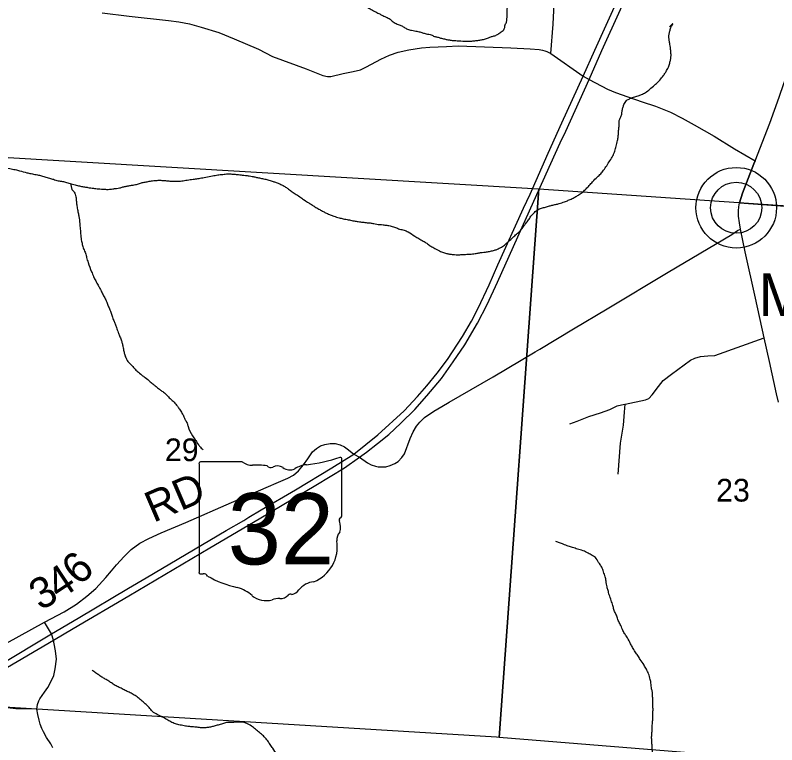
# Model space of a CAD drawing. Extents: x -13.7 to 34, y 0 to 32.3.
# Drawn here: x 27.041 to 28.447, y 18.977 to 20.324 of the extents above; entities that cross this region are included whole.
import ezdxf

# ---------------------------------------------------------------- set-up
doc = ezdxf.new("R2010")
doc.units = 0
for name, color, linetype in [('GM_X_Corporation', 7, 'Continuous'), ('GM_X_County_Road', 7, 'Continuous'), ('GM_X_County_Road_Text', 7, 'Continuous'), ('GM_X_Minor_River', 7, 'Continuous'), ('GM_X_Section_Text', 7, 'Continuous'), ('GM_X_State_Location', 7, 'Continuous'), ('GM_X_State_Route', 7, 'Continuous'), ('GM_X_State_Shield', 7, 'Continuous'), ('GM_X_Township_Road', 7, 'Continuous'), ('GM_X_Unincorporated', 7, 'Continuous'), ('GM_X_Unincorporated_Location', 7, 'Continuous'), ('GM_X_Unincorporated_Text', 7, 'Continuous')]:
    doc.layers.add(name, color=color, linetype=linetype)

msp = doc.modelspace()

# ---------------------------------------------------------------- linework, layer by layer
at = {"layer": 'GM_X_Corporation'}
for points in [[(28.0076, 20.0028), (27.9343, 18.9903), (27.9295, 18.9907), (26.9188, 19.0522), (26.9853, 20.0635)], [(28.0076, 20.0028), (29.0337, 19.933), (28.9612, 18.9069), (27.9343, 18.9903)]]:
    msp.add_lwpolyline(points, close=True, dxfattribs=at)
at = {"layer": 'GM_X_County_Road'}
msp.add_line((27.1077, 19.1812), (27.0948, 19.2028), dxfattribs=at)
for points in [[(27.842, 19.6094), (27.9232, 19.6562), (28.0009, 19.7023), (28.0095, 19.7069), (28.0717, 19.7447), (28.1337, 19.7814), (28.2465, 19.8492), (28.3635, 19.9188), (28.3743, 19.9264), (28.3795, 19.9283)], [(27.5185, 19.4575), (27.5443, 19.4687), (27.5547, 19.4747), (27.5636, 19.4823), (27.5731, 19.4937), (27.5811, 19.5048), (27.5896, 19.5174), (27.5968, 19.5238), (27.6045, 19.5284), (27.6127, 19.5313), (27.622, 19.5329), (27.6315, 19.5327), (27.641, 19.5302), (27.6489, 19.5267), (27.6562, 19.5214), (27.6657, 19.5134), (27.6766, 19.5079), (27.6914, 19.4974), (27.6982, 19.4935), (27.7061, 19.491), (27.7108, 19.49), (27.7177, 19.4898), (27.7251, 19.49), (27.7331, 19.4924), (27.7414, 19.4958), (27.7478, 19.4997), (27.7544, 19.5069), (27.7594, 19.5139), (27.7697, 19.5422), (27.7755, 19.5544), (27.7814, 19.5647), (27.7877, 19.5724), (27.7964, 19.5808), (27.8135, 19.5928), (27.8282, 19.6015), (27.842, 19.6094)], [(27.2189, 19.2978), (27.2281, 19.3088), (27.242, 19.3245), (27.2552, 19.3373), (27.2711, 19.3487), (27.2876, 19.3574), (27.3101, 19.3677), (27.3556, 19.3871), (27.4404, 19.4241), (27.513, 19.4551), (27.5185, 19.4575)], [(26.7689, 19.0326), (26.8253, 19.0552), (26.8652, 19.0766), (26.8873, 19.0892), (26.9488, 19.1225), (27.0948, 19.2028), (27.131, 19.2223), (27.154, 19.2361), (27.1734, 19.251), (27.1897, 19.2652), (27.2083, 19.2853), (27.2189, 19.2978)]]:
    msp.add_lwpolyline(points, dxfattribs=at)
at = {"layer": 'GM_X_Minor_River'}
msp.add_lwpolyline([(27.1427, 20.0128), (27.1457, 20.002)], dxfattribs=at)
for points in [[(27.6709, 20.3481), (27.678, 20.3445), (27.6877, 20.3396), (27.6959, 20.3355), (27.7045, 20.3307), (27.7123, 20.3266), (27.7179, 20.3238), (27.7254, 20.3201), (27.7329, 20.3161), (27.7384, 20.3113), (27.7462, 20.3073), (27.753, 20.3048), (27.7586, 20.3015), (27.7649, 20.2979), (27.7724, 20.2958), (27.7781, 20.2948), (27.7864, 20.293), (27.7928, 20.2913), (27.7992, 20.2892), (27.809, 20.2873), (27.8146, 20.2845), (27.8202, 20.2832), (27.8262, 20.2815), (27.8334, 20.2797), (27.8394, 20.2784), (27.8455, 20.2774), (27.8545, 20.2767), (27.8633, 20.276), (27.8788, 20.2755), (27.8857, 20.2761), (27.8933, 20.2769), (27.9001, 20.2779), (27.9074, 20.2795), (27.9143, 20.2816), (27.9201, 20.284), (27.9262, 20.2857), (27.9324, 20.2889), (27.9382, 20.2929), (27.9437, 20.2984), (27.945, 20.3041), (27.9475, 20.3109), (27.9485, 20.3165), (27.949, 20.3321), (27.9496, 20.3378), (27.9505, 20.3438), (27.9515, 20.3495), (27.9524, 20.3555), (27.9465, 20.3588)], [(28.2495, 20.2697), (28.2482, 20.2766), (28.2476, 20.2827), (28.2478, 20.2884), (28.2492, 20.294), (28.2513, 20.3012), (28.2549, 20.3079), (28.2487, 20.3024)], [(27.6961, 19.9401), (27.7029, 19.9388), (27.7138, 19.9372), (27.7199, 19.9367), (27.7267, 19.9357), (27.735, 19.9343), (27.7429, 19.9317), (27.7504, 19.9288), (27.7586, 19.9266), (27.7661, 19.9237), (27.7788, 19.9157), (27.7859, 19.9113), (27.794, 19.9065), (27.8007, 19.9025), (27.8067, 19.8981), (27.8134, 19.8944), (27.8227, 19.8892), (27.8294, 19.8863), (27.8369, 19.8838), (27.8426, 19.8825), (27.849, 19.8819), (27.8551, 19.8813), (27.8615, 19.8815), (27.8691, 19.882), (27.8802, 19.8824), (27.8897, 19.8836), (27.897, 19.8848), (27.9031, 19.8858), (27.9088, 19.8864), (27.9164, 19.8876), (27.9237, 19.8893), (27.9302, 19.8913), (27.9383, 19.8956), (27.9457, 19.9007), (27.9516, 19.9058), (27.9594, 19.9132), (27.9664, 19.9194), (27.9735, 19.926), (27.9794, 19.9338), (27.9834, 19.9393), (27.9882, 19.9456), (27.993, 19.9523), (27.9977, 19.9578), (28.0043, 19.9637), (28.0105, 19.9665), (28.0182, 19.9689), (28.0255, 19.971), (28.0316, 19.9727), (28.0385, 19.9743), (28.045, 19.9757), (28.055, 19.9791), (28.0619, 19.9819), (28.0692, 19.9851), (28.0758, 19.9887), (28.082, 19.9923), (28.089, 19.9977), (28.0949, 20.0032), (28.1004, 20.0091), (28.1067, 20.0161), (28.1157, 20.025), (28.1216, 20.0308), (28.1271, 20.0375), (28.1327, 20.0457), (28.1387, 20.055), (28.144, 20.0639), (28.1477, 20.0729), (28.1502, 20.0816), (28.1529, 20.0925), (28.1539, 20.0997), (28.1545, 20.1072), (28.1551, 20.1144), (28.1557, 20.1213), (28.1556, 20.1277), (28.1576, 20.1333), (28.1601, 20.1393), (28.1611, 20.1461), (28.1625, 20.1529), (28.1646, 20.1586), (28.1694, 20.166), (28.1756, 20.1696), (28.1848, 20.1731), (28.1925, 20.1755), (28.1986, 20.1779), (28.2063, 20.1822), (28.2145, 20.1888), (28.2231, 20.1961), (28.229, 20.202), (28.2357, 20.2101), (28.2401, 20.2157), (28.2433, 20.2213), (28.2474, 20.2295), (28.2495, 20.237), (28.2509, 20.2431), (28.2515, 20.2491), (28.251, 20.2567), (28.2504, 20.264), (28.2495, 20.2697)], [(26.9187, 20.0593), (26.933, 20.0642), (26.9433, 20.0646), (26.9528, 20.065), (26.9592, 20.0656), (26.9664, 20.065), (26.9736, 20.0628), (26.9803, 20.0603), (26.9904, 20.055), (26.9997, 20.0498), (27.0102, 20.0456), (27.0313, 20.0404), (27.0411, 20.0385), (27.049, 20.0364), (27.0626, 20.0329), (27.0701, 20.0311), (27.0799, 20.0293), (27.0874, 20.0275), (27.0957, 20.025), (27.104, 20.0228), (27.1115, 20.0206), (27.1201, 20.0181), (27.1281, 20.0167), (27.1356, 20.0149), (27.1443, 20.0123), (27.1537, 20.0097), (27.1616, 20.008), (27.1691, 20.0066), (27.1752, 20.0056), (27.1854, 20.0041), (27.1941, 20.0031), (27.2058, 20.0023), (27.2126, 20.0021), (27.221, 20.003), (27.2279, 20.0039), (27.2336, 20.0048), (27.2397, 20.0065), (27.2458, 20.0078), (27.2523, 20.0091), (27.2588, 20.0101), (27.2665, 20.0117), (27.2738, 20.0141), (27.281, 20.0154), (27.2883, 20.0171), (27.2967, 20.0183), (27.305, 20.0188), (27.3141, 20.0185), (27.3221, 20.0178), (27.3308, 20.0172), (27.3411, 20.0172), (27.3509, 20.018), (27.3612, 20.0196), (27.3719, 20.0211), (27.3803, 20.0224), (27.3895, 20.024), (27.4021, 20.0266), (27.4078, 20.0275), (27.417, 20.0291), (27.4265, 20.03), (27.4349, 20.0308), (27.4425, 20.0302), (27.4512, 20.0295), (27.4599, 20.0285), (27.4659, 20.0279), (27.4727, 20.0269), (27.4784, 20.026), (27.4848, 20.0246), (27.492, 20.0232), (27.4995, 20.0215), (27.5074, 20.0197), (27.5153, 20.0171), (27.5213, 20.0154), (27.5277, 20.0129), (27.5344, 20.0097), (27.54, 20.0064), (27.5455, 20.0025), (27.5522, 19.9973), (27.5597, 19.9929), (27.5682, 19.9869), (27.5745, 19.9825), (27.5827, 19.9773), (27.5894, 19.9729), (27.5957, 19.9689), (27.6031, 19.9648), (27.6095, 19.9612), (27.6154, 19.958), (27.6226, 19.9551), (27.6289, 19.9526), (27.6387, 19.9496), (27.6466, 19.9478), (27.6557, 19.946), (27.6643, 19.9442), (27.6723, 19.9428), (27.6802, 19.9418), (27.6885, 19.9407), (27.6961, 19.9401)], [(27.1457, 20.002), (27.1498, 19.997), (27.153, 19.9885), (27.1538, 19.9794), (27.1547, 19.9714), (27.1563, 19.9629), (27.1579, 19.9549), (27.1592, 19.9484), (27.1598, 19.9419), (27.1606, 19.9317), (27.1617, 19.9202), (27.1628, 19.9088), (27.1648, 19.9004), (27.1672, 19.8923), (27.1707, 19.8842), (27.1728, 19.8762), (27.1755, 19.867), (27.1818, 19.85), (27.1856, 19.8408), (27.1895, 19.8331), (27.1938, 19.825), (27.1974, 19.8188), (27.2003, 19.813), (27.2042, 19.8056), (27.2081, 19.7979), (27.2113, 19.7902), (27.2141, 19.7833), (27.2176, 19.7755), (27.22, 19.7679), (27.2228, 19.7598), (27.2256, 19.7536), (27.2277, 19.7471), (27.2312, 19.7379), (27.2336, 19.7317), (27.2364, 19.724), (27.2385, 19.7179), (27.2398, 19.7118), (27.2414, 19.7033), (27.2431, 19.6965), (27.2455, 19.6903), (27.2488, 19.6845), (27.2546, 19.6786), (27.2609, 19.6712), (27.2668, 19.666), (27.2745, 19.6593), (27.2808, 19.6546), (27.29, 19.647), (27.2967, 19.6415), (27.3022, 19.6371), (27.3089, 19.6316), (27.3148, 19.6276), (27.3204, 19.6225), (27.327, 19.6158), (27.3343, 19.6091), (27.3402, 19.6021), (27.3442, 19.5962), (27.3488, 19.5889), (27.3524, 19.5823), (27.3549, 19.5765), (27.3581, 19.5707), (27.3602, 19.5642), (27.368, 19.5472), (27.3734, 19.5398), (27.377, 19.5336)], [(27.377, 19.5336), (27.3814, 19.5278), (27.3876, 19.5211)], [(28.2164, 18.9767), (28.2159, 18.9847), (28.2158, 18.9934), (28.2165, 19.0014), (28.217, 19.0162), (28.218, 19.0241), (28.2179, 19.0325), (28.2182, 19.0408), (28.2181, 19.0492), (28.218, 19.0572), (28.2175, 19.0651), (28.217, 19.0735), (28.2157, 19.08), (28.2145, 19.0903), (28.2132, 19.0972), (28.2102, 19.1079), (28.2059, 19.1164), (28.2016, 19.1238), (28.1947, 19.1343), (28.19, 19.1413), (28.1853, 19.1483), (28.1806, 19.1564), (28.1767, 19.163), (28.171, 19.1742), (28.1666, 19.1808), (28.1627, 19.1874), (28.1588, 19.1966), (28.1549, 19.2044), (28.1521, 19.2121), (28.1489, 19.2194), (28.1461, 19.2263), (28.1441, 19.2336), (28.141, 19.2432), (28.1375, 19.2536), (28.1352, 19.2616), (28.1335, 19.2681), (28.1316, 19.2788), (28.1299, 19.2869), (28.1268, 19.2961), (28.1237, 19.3045), (28.1193, 19.3111), (28.1136, 19.3204), (28.1062, 19.3264), (28.0987, 19.3304), (28.089, 19.3349), (28.0788, 19.3379), (28.0698, 19.3409), (28.0619, 19.3434), (28.0526, 19.3468), (28.0458, 19.3493), (28.0387, 19.3522)], [(27.4309, 19.0175), (27.4236, 19.0155), (27.4155, 19.0131), (27.4083, 19.011), (27.4014, 19.0094), (27.3945, 19.0084), (27.3876, 19.0079), (27.3786, 19.0086), (27.3702, 19.0096), (27.3631, 19.0102), (27.3555, 19.0113), (27.3453, 19.0131), (27.3366, 19.0153), (27.328, 19.019), (27.3206, 19.0234), (27.3124, 19.0279), (27.3031, 19.0327), (27.2945, 19.038), (27.2879, 19.0454), (27.2809, 19.0525), (27.2736, 19.0588), (27.2658, 19.0651), (27.2584, 19.0696), (27.2513, 19.0736), (27.2438, 19.0769), (27.2367, 19.0809), (27.2292, 19.0842), (27.2218, 19.0886), (27.2155, 19.093), (27.2088, 19.097), (27.2024, 19.1007), (27.1958, 19.1051), (27.1894, 19.1094), (27.1828, 19.1142)], [(28.0645, 18.3997), (28.0617, 18.407), (28.0555, 18.4167), (28.0485, 18.4234), (28.0422, 18.4281), (28.0359, 18.431), (28.0288, 18.4343), (28.0224, 18.436), (28.0156, 18.4377), (28.0088, 18.4399), (28.0007, 18.4455), (27.9936, 18.451), (27.9867, 18.4588), (27.979, 18.4659), (27.9726, 18.4699), (27.9676, 18.4792), (27.9638, 18.4885), (27.9606, 18.495), (27.9582, 18.5031), (27.9529, 18.5151), (27.9463, 18.5236), (27.9413, 18.5322), (27.9381, 18.5391), (27.933, 18.5469), (27.9268, 18.5543), (27.9206, 18.5606), (27.9111, 18.5704), (27.9044, 18.5771), (27.8982, 18.5841), (27.889, 18.5924), (27.8843, 18.599), (27.8784, 18.606), (27.8711, 18.6131), (27.8637, 18.6194), (27.8574, 18.6235), (27.8478, 18.6314), (27.8306, 18.6403), (27.8224, 18.6459), (27.8161, 18.6503), (27.8087, 18.6543), (27.802, 18.6595), (27.7913, 18.6671), (27.7849, 18.6699), (27.7775, 18.677), (27.7705, 18.6818), (27.762, 18.6889), (27.7539, 18.696), (27.7476, 18.7023), (27.7414, 18.7078), (27.7336, 18.7146), (27.7236, 18.7221), (27.7147, 18.7285), (27.7055, 18.7353), (27.6954, 18.7417), (27.6872, 18.7465), (27.6798, 18.7505), (27.6734, 18.7542), (27.6648, 18.7586), (27.6585, 18.7611), (27.6511, 18.7663), (27.6444, 18.7722), (27.6389, 18.7789), (27.635, 18.7862), (27.6308, 18.797), (27.6263, 18.8085), (27.6223, 18.8163), (27.6184, 18.8236), (27.6138, 18.8325), (27.611, 18.8391), (27.6047, 18.8465), (27.6004, 18.8538), (27.5965, 18.8608), (27.5915, 18.8693), (27.5868, 18.8771), (27.5836, 18.884), (27.5767, 18.8922), (27.5709, 18.9008), (27.565, 18.9086), (27.5585, 18.9156), (27.549, 18.9273), (27.5417, 18.936), (27.5354, 18.9419), (27.5296, 18.9508), (27.5246, 18.9586), (27.5162, 18.9702), (27.5115, 18.9772), (27.5072, 18.9838), (27.5006, 18.9916), (27.494, 18.9976), (27.4862, 19.0039), (27.4792, 19.0098), (27.4699, 19.0151), (27.4635, 19.0179), (27.4533, 19.0183), (27.4468, 19.0181), (27.4381, 19.0176), (27.4309, 19.0175)], [(28.7426, 18.3371), (28.7453, 18.3604), (28.7453, 18.3703), (28.7447, 18.3767), (28.7446, 18.3836), (28.7449, 18.3931), (28.7439, 18.4091), (28.7419, 18.419), (28.739, 18.4328), (28.7363, 18.4431), (28.734, 18.4535), (28.7302, 18.4665), (28.7271, 18.475), (28.7214, 18.4881), (28.7175, 18.4958), (28.7139, 18.5024), (28.7096, 18.5094), (28.7049, 18.5167), (28.6999, 18.5245), (28.6941, 18.5327), (28.6894, 18.5393), (28.6831, 18.5467), (28.6744, 18.5573), (28.6678, 18.5651), (28.6613, 18.5752), (28.6566, 18.5818), (28.65, 18.5896), (28.6419, 18.5978), (28.6335, 18.6065), (28.6265, 18.6124), (28.6161, 18.6196), (28.6086, 18.624), (28.5982, 18.6304), (28.5907, 18.6337), (28.5826, 18.6393), (28.5762, 18.643), (28.5688, 18.6474), (28.5617, 18.651), (28.5545, 18.6517), (28.5466, 18.6523), (28.5382, 18.6522), (28.5318, 18.6528), (28.5238, 18.6527), (28.5173, 18.6521), (28.5102, 18.6531), (28.5001, 18.6592), (28.4934, 18.6643), (28.486, 18.6691), (28.4797, 18.6735), (28.4731, 18.679), (28.4638, 18.6851), (28.4548, 18.691), (28.4448, 18.6971), (28.4344, 18.7027), (28.4261, 18.7068), (28.4172, 18.7121), (28.4098, 18.7165), (28.4034, 18.7193), (28.3959, 18.7215), (28.3883, 18.7233), (28.3717, 18.7261), (28.3653, 18.7278), (28.3589, 18.7292), (28.3522, 18.7324), (28.3433, 18.7388), (28.3359, 18.7451), (28.3256, 18.7557), (28.3191, 18.7632), (28.3122, 18.7729), (28.3042, 18.7834), (28.2958, 18.7951), (28.2871, 18.8075), (28.2809, 18.8153), (28.2762, 18.8227), (28.2716, 18.8328), (28.2666, 18.8417), (28.2623, 18.849), (28.2581, 18.8583), (28.2519, 18.8684), (28.2469, 18.8761), (28.2422, 18.8846), (28.2379, 18.892), (28.233, 18.9036), (28.2298, 18.9109), (28.2271, 18.9193), (28.2243, 18.927), (28.2222, 18.9343), (28.2203, 18.9435), (28.219, 18.9511), (28.2178, 18.9595), (28.2169, 18.9675), (28.2164, 18.9767)]]:
    msp.add_spline(points, degree=3, dxfattribs=at)
at = {"layer": 'GM_X_State_Route'}
for points in [[(27.01, 19.1233), (27.1077, 19.1812), (27.1572, 19.2103), (27.25, 19.2656), (27.2827, 19.2846), (27.4304, 19.3722), (27.4629, 19.3907), (27.472, 19.3967), (27.495, 19.4103), (27.5581, 19.4475), (27.6252, 19.4878), (27.6657, 19.5134), (27.7103, 19.5487), (27.7589, 19.5935), (27.7837, 19.6195), (27.8005, 19.6391), (27.8198, 19.6628), (27.8386, 19.6882), (27.8665, 19.7304), (27.883, 19.759), (27.8952, 19.7827), (27.9156, 19.8258), (27.932, 19.8628), (27.9794, 19.9675), (27.9914, 19.9932), (28.025, 20.0686), (28.0502, 20.1246), (28.089, 20.2111), (28.1107, 20.2589), (28.1799, 20.4118)], [(27.1115, 19.1698), (27.148, 19.1913), (27.2504, 19.2519), (27.4, 19.3401), (27.4915, 19.3941), (27.5957, 19.4557), (27.6487, 19.4882), (27.6766, 19.5079), (27.6896, 19.5171), (27.7098, 19.5329), (27.7303, 19.5498), (27.7527, 19.5702), (27.7783, 19.5956), (27.8009, 19.6206), (27.8276, 19.6531), (27.8496, 19.6835), (27.8711, 19.7149), (27.8943, 19.7549), (27.9118, 19.7894), (27.931, 19.8308), (27.9983, 19.9804), (28.0469, 20.088), (28.0574, 20.1094), (28.1001, 20.2052), (28.1237, 20.2584), (28.1928, 20.4107)], [(28.4068, 20.0545), (28.4336, 20.1245), (28.451, 20.1726), (28.46, 20.1976), (28.4875, 20.266), (28.4918, 20.2768), (28.4987, 20.2891), (28.5144, 20.3129), (28.5197, 20.3203)], [(28.3778, 19.9772), (28.3832, 19.9948), (28.4045, 20.0491), (28.4068, 20.0545)], [(28.4498, 19.6089), (28.4459, 19.6248), (28.4332, 19.6843), (28.4236, 19.7279), (28.4075, 19.801), (28.3886, 19.8867), (28.3795, 19.9283), (28.3778, 19.9403), (28.3762, 19.9525), (28.3762, 19.9624), (28.3764, 19.9698), (28.3778, 19.9772)], [(27.0848, 19.0577), (27.0865, 19.0613), (27.095, 19.0735), (27.1014, 19.0823), (27.1067, 19.0927), (27.112, 19.1045), (27.1149, 19.1171), (27.1171, 19.1345), (27.1155, 19.1504), (27.1129, 19.1629), (27.1115, 19.1698), (27.1077, 19.1812)], [(25.8514, 18.5518), (26.0363, 18.5692), (26.1609, 18.5805), (26.226, 18.5865), (26.2529, 18.5899), (26.2667, 18.5928), (26.2882, 18.5966), (26.3274, 18.608), (26.3676, 18.6252), (26.3967, 18.6413), (26.4234, 18.6599), (26.4781, 18.7064), (26.5952, 18.8099), (26.6462, 18.856), (26.7189, 18.9201), (26.7435, 18.9401), (26.7676, 18.9584), (26.7872, 18.9731), (26.8234, 18.9975), (26.8466, 19.0127), (26.8737, 19.0286), (27.0165, 19.1136), (27.1115, 19.1698)], [(27.1104, 18.9711), (27.1067, 18.9784), (27.0989, 18.9901), (27.093, 19.0007), (27.0898, 19.007), (27.0871, 19.0148), (27.0849, 19.0219), (27.0824, 19.0323), (27.081, 19.0426), (27.0818, 19.0513), (27.0848, 19.0577)]]:
    msp.add_lwpolyline(points, dxfattribs=at)
at = {"layer": 'GM_X_State_Shield'}
for p, q in [((27.46, 19.499), (27.3828, 19.499)), ((27.6439, 19.3993), (27.6439, 19.504)), ((27.3802, 19.4956), (27.3802, 19.2955)), ((27.6438, 19.3993), (27.6439, 19.3993))]:
    msp.add_line(p, q, dxfattribs=at)
for centre, radius, start, end in [((27.3832, 19.496), 0.00305, 98.1301, 188.1301), ((27.4784, 19.5223), 0.0296, 231.6195, 271.1119), ((27.5499, 19.7719), 0.2796, 275.8445, 288.9065), ((27.6409, 19.5044), 0.00294, 351.8621, 97.738), ((27.4882, 19.3867), 0.1064, 80.4867, 94.9883), ((27.5124, 19.4971), 0.00855, 219.7921, 297.1024), ((27.5249, 19.4739), 0.0178, 54.4667, 119.1411), ((27.5478, 19.5056), 0.0214, 233.8562, 294.8282), ((27.5856, 19.4379), 0.0563, 97.3462, 120.7689), ((27.6407, 19.3989), 0.00314, 289.6038, 7.7341), ((27.6432, 19.3916), 0.00454, 107.944, 210.337), ((27.6143, 19.3784), 0.0273, 340.033, 23.6496), ((27.6544, 19.3555), 0.0198, 136.8065, 186.9296), ((27.5656, 19.3422), 0.0699, 292.3089, 8.9858), ((27.3832, 19.295), 0.00308, 171.9584, 258.3066), ((27.3837, 19.3155), 0.0235, 267.339, 280.6039), ((27.3885, 19.2839), 0.00848, 29.7484, 93.2717), ((27.4956, 19.4637), 0.2019, 240.4129, 257.1985), ((27.5951, 19.2393), 0.0383, 94.4031, 142.5768), ((27.4354, 19.2056), 0.0632, 47.1842, 75.836), ((27.5466, 19.2761), 0.0226, 282.8732, 323.2771), ((27.5037, 19.2829), 0.0401, 230.7004, 286.2918), ((27.5269, 19.2137), 0.0329, 85.6951, 111.2099), ((27.5298, 19.2679), 0.0214, 268.777, 315.5493), ((27.5491, 19.2486), 0.00601, 65.7517, 132.6484)]:
    msp.add_arc(centre, radius, start, end, dxfattribs=at)
at = {"layer": 'GM_X_Township_Road'}
msp.add_line((28.0294, 20.2529), (28.089, 20.2111), dxfattribs=at)
for points in [[(28.0294, 20.2529), (28.0337, 20.3068), (28.0358, 20.3449), (28.0423, 20.4405), (28.049, 20.5506)], [(27.2013, 20.3282), (27.2511, 20.3217), (27.3236, 20.3138), (27.343, 20.3114), (27.3625, 20.3077), (27.3842, 20.3013), (27.4166, 20.2915), (27.4454, 20.2801), (27.4903, 20.2608), (27.516, 20.2473), (27.5779, 20.2247), (27.6085, 20.2125), (27.6174, 20.2107), (27.6237, 20.2105), (27.646, 20.216), (27.6647, 20.2196), (27.6781, 20.223), (27.6894, 20.2282), (27.7157, 20.2427), (27.7317, 20.2496), (27.748, 20.2553), (27.7674, 20.2595), (27.7908, 20.2631), (27.8061, 20.2643), (27.837, 20.266), (27.8585, 20.2669), (27.9558, 20.2633), (27.9917, 20.2615), (28.008, 20.2605), (28.014, 20.2592), (28.0185, 20.2581), (28.0222, 20.2564), (28.0294, 20.2529)], [(28.089, 20.2111), (28.1001, 20.2052), (28.1345, 20.1871), (28.149, 20.1807), (28.1717, 20.1728), (28.1981, 20.1638), (28.2231, 20.1555), (28.2502, 20.1443), (28.2721, 20.1336), (28.294, 20.1212), (28.3313, 20.1001), (28.3689, 20.0768), (28.4068, 20.0545)], [(28.3778, 19.9772), (28.4538, 19.9719), (28.5533, 19.9651), (28.6689, 19.9588), (28.794, 19.9508), (28.8413, 19.948), (28.9373, 19.9418), (29.0413, 19.9358), (29.0461, 20.023), (29.0533, 20.1455), (29.0533, 20.1547), (29.0512, 20.16)], [(28.4068, 20.0545), (28.4045, 20.0491), (28.3832, 19.9948), (28.3778, 19.9772)], [(28.1659, 19.6056), (28.1669, 19.6058), (28.2044, 19.6134), (28.2105, 19.6162), (28.2167, 19.6229), (28.2281, 19.6381), (28.2371, 19.6495), (28.2523, 19.6609), (28.2875, 19.6865), (28.2956, 19.6903), (28.306, 19.6932), (28.3193, 19.6946), (28.3326, 19.6955), (28.4236, 19.7279)], [(28.0647, 19.5692), (28.0785, 19.5744), (28.0999, 19.5825), (28.1213, 19.5892), (28.1384, 19.5958), (28.1521, 19.6025), (28.1602, 19.6044), (28.1659, 19.6056)], [(28.1536, 19.4761), (28.1583, 19.5336), (28.1635, 19.5668), (28.1654, 19.5906), (28.1669, 19.6058)], [(27.081, 19.0426), (27.0586, 19.0431), (27.0418, 19.0431), (27.0265, 19.0451), (27.0177, 19.0458), (27.0051, 19.0473), (26.9866, 19.048), (26.9753, 19.048), (26.9637, 19.0473), (26.9533, 19.0451), (26.9462, 19.0426), (26.9383, 19.0391), (26.9257, 19.0322), (26.9188, 19.0283)]]:
    msp.add_lwpolyline(points, dxfattribs=at)
at = {"layer": 'GM_X_Unincorporated'}
for radius in [0.0744, 0.0472]:
    msp.add_circle((28.3718, 19.9681), radius, dxfattribs=at)
at = {"layer": 'GM_X_Unincorporated_Location'}
msp.add_line((28.3718, 19.9681), (28.3718, 19.9681), dxfattribs=at)

# ---------------------------------------------------------------- texts
at = {"layer": 'GM_X_County_Road_Text'}
for s, height, rotation, p in [('RD', 0.05682, 23.2643, (27.296, 19.3862)), ('6', 0.0568, 42.7907, (27.1591, 19.2686)), ('4', 0.0568, 33.3694, (27.1219, 19.243)), ('3', 0.0568, 29.0852, (27.0873, 19.2236))]:
    msp.add_text(s, height=height, rotation=rotation, dxfattribs=at).set_placement(p)
at = {"layer": 'GM_X_Section_Text'}
for s, p in [('29', (27.3172, 19.5003)), ('23', (28.3347, 19.4257))]:
    msp.add_text(s, height=0.04186, rotation=0, dxfattribs=at).set_placement(p)
at = {"layer": 'GM_X_State_Location'}
for s, p in [('s', (27.5091, 19.3822)), ('r', (27.509, 19.3822))]:
    msp.add_text(s, height=0.000189, dxfattribs=at).set_placement(p)
msp.add_text('32', height=0.000189, rotation=0, dxfattribs=at).set_placement((27.4614, 19.3684))
at = {"layer": 'GM_X_State_Shield'}
msp.add_text('32', height=0.13184, dxfattribs=at).set_placement((27.4333, 19.3096))
at = {"layer": 'GM_X_Unincorporated_Text'}
msp.add_text('Mount Blanco', height=0.078977, rotation=0, dxfattribs=at).set_placement((28.413, 19.7681))

doc.saveas('drawing.dxf')
